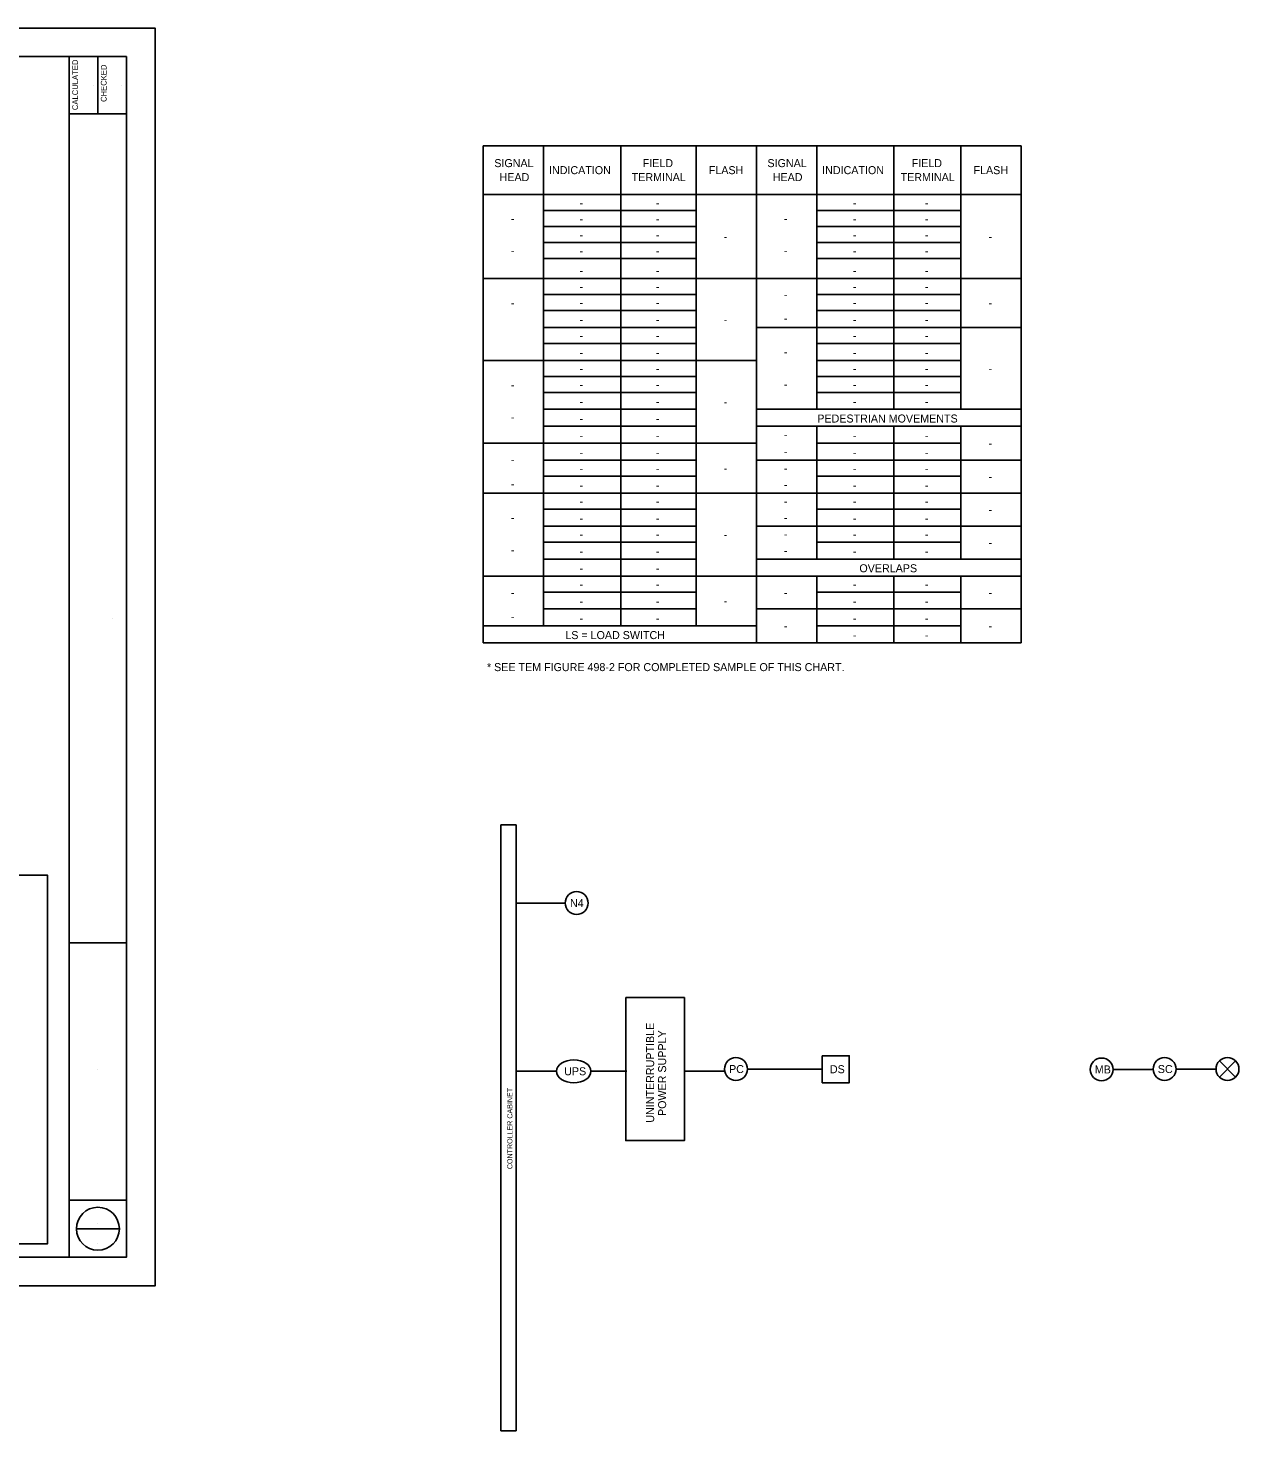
# Model space of a CAD drawing. Extents: x 32.6 to 95.8, y 11.4 to 49.5.
# Drawn here: x 74.62 to 95.79, y 24.93 to 49.47 of the extents above; entities that cross this region are included whole.
import ezdxf

# ---------------------------------------------------------------- set-up
doc = ezdxf.new("R2010")
doc.units = 0
for name, color, linetype in [('SG_P_Text', 7, 'Continuous'), ('SH_Border', 7, 'Continuous'), ('SH_Cut_Line', 7, 'Continuous'), ('SH_Data', 7, 'Continuous'), ('SH_Text', 7, 'Continuous'), ('ST_Text', 7, 'Continuous')]:
    doc.layers.add(name, color=color, linetype=linetype)

msp = doc.modelspace()

# ---------------------------------------------------------------- linework, layer by layer
at = {"layer": 'SG_P_Text'}
for p, q in [((83.858, 31.225), (83.631, 31.225)), ((84.685, 31.225), (84.458, 31.225)), ((95.447, 31.406), (95.73, 31.123)), ((95.447, 31.123), (95.73, 31.406))]:
    msp.add_line(p, q, dxfattribs=at)
msp.add_lwpolyline([(88.503, 31.498), (88.976, 31.498), (88.976, 31.024), (88.503, 31.024)], close=True, dxfattribs=at)
for centre in [(84.208, 34.168), (86.994, 31.264), (93.387, 31.257), (94.488, 31.264), (95.588, 31.264)]:
    msp.add_circle(centre, 0.2, dxfattribs=at)
msp.add_ellipse((84.158, 31.225), major_axis=(0.3, 0), ratio=0.666667, dxfattribs=at)
at = {"layer": 'SH_Border'}
for p, q in [((75.337, 27.971), (75.337, 48.971)), ((75.837, 48.971), (75.837, 47.971)), ((75.337, 47.971), (76.337, 47.971)), ((75.337, 33.471), (76.337, 33.471)), ((75.337, 28.971), (76.337, 28.971))]:
    msp.add_line(p, q, dxfattribs=at)
msp.add_lwpolyline([(44.837, 48.971), (76.337, 48.971), (76.337, 27.971), (44.837, 27.971)], close=True, dxfattribs=at)
at = {"layer": 'SH_Cut_Line'}
msp.add_lwpolyline([(42.837, 27.471), (76.837, 27.471), (76.837, 49.471), (42.837, 49.471)], close=True, dxfattribs=at)
at = {"layer": 'SH_Data'}
for p, q in [((75.757, 48.475), (75.757, 48.475)), ((76.257, 48.475), (76.257, 48.475)), ((76.087, 39.138), (76.087, 39.138)), ((82.88, 35.535), (82.88, 24.934)), ((83.153, 35.535), (82.88, 35.535)), ((83.153, 24.934), (83.153, 35.535)), ((84.008, 34.168), (83.169, 34.168)), ((75.837, 31.263), (75.837, 31.263)), ((83.153, 31.225), (83.631, 31.225)), ((84.685, 31.225), (85.085, 31.225)), ((86.811, 31.225), (86.111, 31.225)), ((87.194, 31.264), (88.503, 31.264)), ((93.587, 31.257), (94.287, 31.257)), ((94.688, 31.264), (95.388, 31.264)), ((75.462, 28.471), (76.212, 28.471)), ((75.837, 28.556), (75.837, 28.556)), ((75.837, 28.216), (75.837, 28.216)), ((82.88, 24.934), (83.153, 24.934))]:
    msp.add_line(p, q, dxfattribs=at)
for points in [[(55.099, 34.655), (74.956, 34.655), (74.956, 28.209), (55.099, 28.209)], [(85.068, 32.514), (86.094, 32.514), (86.094, 30.014), (85.068, 30.014)]]:
    msp.add_lwpolyline(points, close=True, dxfattribs=at)
msp.add_circle((75.837, 28.471), 0.375, dxfattribs=at)
at = {"layer": 'ST_Text'}
for p, q in [((82.574, 47.414), (91.979, 47.414)), ((82.574, 47.414), (82.574, 38.718)), ((83.628, 47.414), (83.628, 39.014)), ((84.979, 47.414), (84.979, 39.014)), ((86.297, 47.414), (86.297, 39.014)), ((87.351, 47.414), (87.351, 38.718)), ((88.405, 47.414), (88.405, 42.803)), ((89.755, 47.414), (89.755, 42.803)), ((90.925, 47.414), (90.925, 42.803)), ((91.979, 47.414), (91.979, 38.718)), ((82.574, 46.558), (91.979, 46.558)), ((83.628, 46.278), (86.297, 46.278)), ((88.405, 46.278), (90.925, 46.278)), ((83.628, 45.998), (86.297, 45.998)), ((88.405, 45.998), (90.925, 45.998)), ((83.628, 45.718), (86.297, 45.718)), ((88.405, 45.718), (90.925, 45.718)), ((83.628, 45.438), (86.297, 45.438)), ((88.405, 45.438), (90.925, 45.438)), ((82.574, 45.092), (91.979, 45.092)), ((83.628, 44.812), (86.297, 44.812)), ((88.405, 44.812), (90.925, 44.812)), ((83.628, 44.532), (86.297, 44.532)), ((88.405, 44.532), (90.925, 44.532)), ((83.628, 44.236), (86.297, 44.236)), ((87.351, 44.236), (91.979, 44.236)), ((83.628, 43.956), (86.297, 43.956)), ((88.405, 43.956), (90.925, 43.956)), ((82.574, 43.659), (87.351, 43.659)), ((88.405, 43.659), (90.925, 43.659)), ((83.628, 43.379), (86.297, 43.379)), ((88.405, 43.379), (90.925, 43.379)), ((83.628, 43.099), (86.297, 43.099)), ((88.405, 43.099), (90.925, 43.099)), ((83.628, 42.803), (86.297, 42.803)), ((87.351, 42.803), (91.979, 42.803)), ((83.628, 42.506), (86.297, 42.506)), ((87.351, 42.506), (91.979, 42.506)), ((88.405, 42.506), (88.405, 40.184)), ((89.755, 42.506), (89.755, 40.184)), ((90.925, 42.506), (90.925, 40.184)), ((82.574, 42.21), (87.351, 42.21)), ((88.405, 42.21), (90.925, 42.21)), ((83.628, 41.913), (86.297, 41.913)), ((87.351, 41.913), (91.979, 41.913)), ((83.628, 41.633), (86.297, 41.633)), ((88.405, 41.633), (90.925, 41.633)), ((82.574, 41.337), (91.979, 41.337)), ((83.628, 41.057), (86.297, 41.057)), ((88.405, 41.057), (90.925, 41.057)), ((83.628, 40.76), (86.297, 40.76)), ((87.351, 40.76), (91.979, 40.76)), ((83.628, 40.48), (86.297, 40.48)), ((88.405, 40.48), (90.925, 40.48)), ((83.628, 40.184), (86.297, 40.184)), ((87.351, 40.184), (91.979, 40.184)), ((82.574, 39.887), (91.979, 39.887)), ((88.405, 39.887), (88.405, 38.718)), ((89.755, 39.887), (89.755, 38.718)), ((90.925, 39.887), (90.925, 38.718)), ((83.628, 39.607), (86.297, 39.607)), ((88.405, 39.607), (90.925, 39.607)), ((83.628, 39.311), (86.297, 39.311)), ((87.351, 39.311), (91.979, 39.311)), ((82.574, 39.014), (87.351, 39.014)), ((88.405, 39.014), (90.925, 39.014)), ((82.574, 38.718), (91.979, 38.718))]:
    msp.add_line(p, q, dxfattribs=at)

# ---------------------------------------------------------------- texts
at = {"layer": 'SG_P_Text'}
for s, p in [('N4', (84.092, 34.098)), ('UPS', (83.99, 31.155)), ('DS', (88.636, 31.191))]:
    msp.add_text(s, height=0.14, dxfattribs=at).set_placement(p)
for s, p in [('PC', (86.873, 31.194)), ('MB', (93.268, 31.187)), ('SC', (94.37, 31.194))]:
    msp.add_text(s, height=0.14, rotation=360, dxfattribs=at).set_placement(p)
at = {"layer": 'SH_Data'}
for s, p in [('CALCULATED', (75.489, 48.036)), ('CHECKED', (75.989, 48.179))]:
    msp.add_text(s, height=0.1, rotation=90, dxfattribs=at).set_placement(p)
at = {"layer": 'SH_Text'}
for s, height, p in [('UNINTERRUPTIBLE', 0.14, (85.563, 30.326)), ('POWER SUPPLY', 0.14, (85.773, 30.443)), ('CONTROLLER CABINET', 0.08993, (83.085, 29.513))]:
    msp.add_text(s, height=height, rotation=90, dxfattribs=at).set_placement(p)
at = {"layer": 'ST_Text'}
for s, p in [('SIGNAL', (82.768, 47.039)), ('FIELD', (85.363, 47.039)), ('SIGNAL', (87.545, 47.039)), ('FIELD', (90.066, 47.039)), ('HEAD', (82.861, 46.794)), ('INDICATION', (83.725, 46.916)), ('TERMINAL', (85.17, 46.794)), ('FLASH', (86.519, 46.916)), ('HEAD', (87.637, 46.794)), ('INDICATION', (88.501, 46.916)), ('TERMINAL', (89.873, 46.794)), ('FLASH', (91.148, 46.916)), ('-', (84.26, 46.344)), ('-', (85.594, 46.344)), ('-', (89.037, 46.344)), ('-', (90.297, 46.344)), ('-', (83.058, 46.068)), ('-', (87.834, 46.068)), ('-', (84.26, 46.064)), ('-', (85.594, 46.064)), ('-', (89.037, 46.064)), ('-', (90.297, 46.064)), ('-', (84.26, 45.784)), ('-', (85.594, 45.784)), ('-', (86.78, 45.755)), ('-', (89.037, 45.784)), ('-', (90.297, 45.784)), ('-', (91.408, 45.755)), ('-', (83.058, 45.512)), ('-', (84.26, 45.504)), ('-', (85.594, 45.504)), ('-', (87.834, 45.512)), ('-', (89.037, 45.504)), ('-', (90.297, 45.504)), ('-', (84.26, 45.158)), ('-', (85.594, 45.158)), ('-', (89.037, 45.158)), ('-', (90.297, 45.158)), ('-', (84.26, 44.878)), ('-', (85.594, 44.878)), ('-', (89.037, 44.878)), ('-', (90.297, 44.878)), ('-', (84.26, 44.598)), ('-', (85.594, 44.598)), ('-', (87.834, 44.742)), ('-', (89.037, 44.598)), ('-', (90.297, 44.598)), ('-', (83.058, 44.594)), ('-', (91.408, 44.594)), ('-', (84.26, 44.301)), ('-', (85.594, 44.301)), ('-', (86.78, 44.306)), ('-', (87.834, 44.326)), ('-', (89.037, 44.301)), ('-', (90.297, 44.301)), ('-', (84.26, 44.021)), ('-', (85.594, 44.021)), ('-', (89.037, 44.021)), ('-', (90.297, 44.021)), ('-', (84.26, 43.725)), ('-', (85.594, 43.725)), ('-', (87.834, 43.737)), ('-', (89.037, 43.725)), ('-', (90.297, 43.725)), ('-', (84.26, 43.445)), ('-', (85.594, 43.445)), ('-', (89.037, 43.445)), ('-', (90.297, 43.445)), ('-', (91.408, 43.449)), ('-', (83.058, 43.161)), ('-', (84.26, 43.165)), ('-', (85.594, 43.165)), ('-', (87.834, 43.173)), ('-', (89.037, 43.165)), ('-', (90.297, 43.165)), ('-', (84.26, 42.869)), ('-', (85.594, 42.869)), ('-', (86.78, 42.864)), ('PEDESTRIAN MOVEMENTS', (88.416, 42.572)), ('-', (89.037, 42.869)), ('-', (90.297, 42.869)), ('-', (83.058, 42.597)), ('-', (84.26, 42.572)), ('-', (85.594, 42.572)), ('-', (84.26, 42.276)), ('-', (85.594, 42.276)), ('-', (87.834, 42.288)), ('-', (89.037, 42.276)), ('-', (90.297, 42.276)), ('-', (84.26, 41.979)), ('-', (85.594, 41.979)), ('-', (87.834, 41.991)), ('-', (89.037, 41.979)), ('-', (90.297, 41.979)), ('-', (91.408, 42.14)), ('-', (83.058, 41.851)), ('-', (84.26, 41.699)), ('-', (85.594, 41.699)), ('-', (86.78, 41.703)), ('-', (87.834, 41.703)), ('-', (89.037, 41.699)), ('-', (90.297, 41.699)), ('-', (83.058, 41.427)), ('-', (87.834, 41.415)), ('-', (91.408, 41.555)), ('-', (84.26, 41.403)), ('-', (85.594, 41.403)), ('-', (89.037, 41.403)), ('-', (90.297, 41.403)), ('-', (84.26, 41.123)), ('-', (85.594, 41.123)), ('-', (87.834, 41.127)), ('-', (89.037, 41.123)), ('-', (90.297, 41.123)), ('-', (91.408, 40.979)), ('-', (83.058, 40.839)), ('-', (84.26, 40.826)), ('-', (85.594, 40.826)), ('-', (87.834, 40.839)), ('-', (89.037, 40.826)), ('-', (90.297, 40.826)), ('-', (84.26, 40.546)), ('-', (85.594, 40.546)), ('-', (86.78, 40.542)), ('-', (87.834, 40.55)), ('-', (89.037, 40.546)), ('-', (90.297, 40.546)), ('-', (83.058, 40.274)), ('-', (84.26, 40.25)), ('-', (85.594, 40.25)), ('-', (87.834, 40.262)), ('-', (89.037, 40.25)), ('-', (90.297, 40.25)), ('-', (91.408, 40.402)), ('-', (84.26, 39.953)), ('-', (85.594, 39.953)), ('OVERLAPS', (89.152, 39.953)), ('-', (83.058, 39.529)), ('-', (84.26, 39.673)), ('-', (85.594, 39.673)), ('-', (87.834, 39.529)), ('-', (89.037, 39.673)), ('-', (90.297, 39.673)), ('-', (91.408, 39.529)), ('-', (84.26, 39.377)), ('-', (85.594, 39.377)), ('-', (86.78, 39.381)), ('-', (89.037, 39.377)), ('-', (90.297, 39.377)), ('-', (83.058, 39.105)), ('-', (84.26, 39.08)), ('-', (85.594, 39.08)), ('-', (89.037, 39.08)), ('-', (90.297, 39.08)), ('LS = LOAD SWITCH', (84.01, 38.784)), ('-', (87.834, 38.944)), ('-', (89.037, 38.784)), ('-', (90.297, 38.784)), ('-', (91.408, 38.944)), ('* SEE TEM FIGURE 498-2 FOR COMPLETED SAMPLE OF THIS CHART.', (82.64, 38.224))]:
    msp.add_text(s, height=0.14, dxfattribs=at).set_placement(p)

doc.saveas('drawing.dxf')
